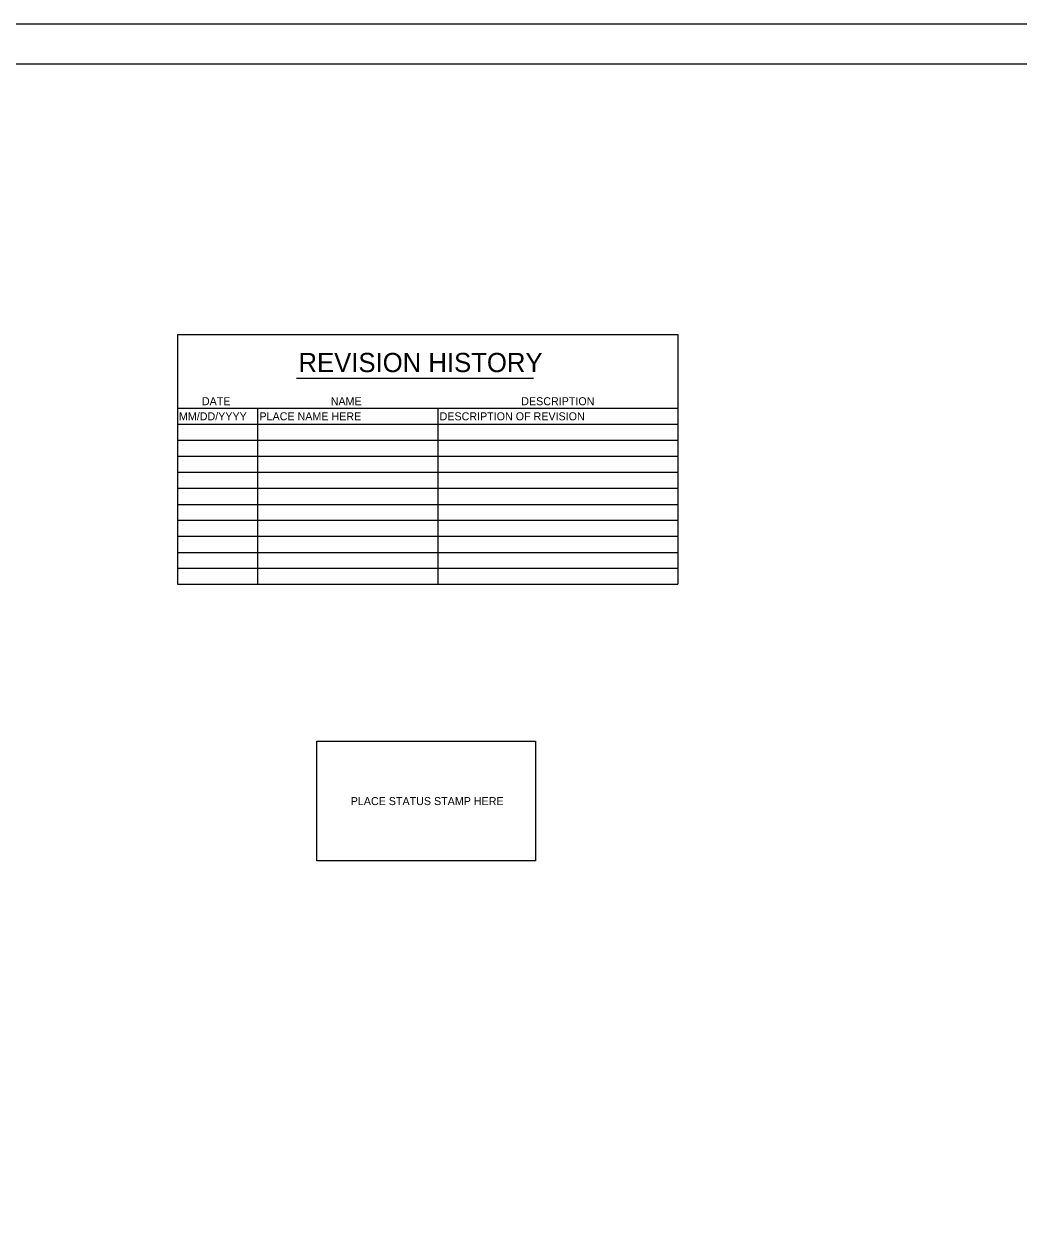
# Model space of a CAD drawing. Extents: x -1.2 to 17.3, y -1 to 2.5.
# Drawn here: x 0.975 to 2.01, y 0.739 to 2 of the extents above; entities that cross this region are included whole.
import ezdxf

# ---------------------------------------------------------------- set-up
doc = ezdxf.new("R2010")
doc.units = 0
for name, color, linetype in [('#plot_shape', 7, 'Continuous'), ('P_ODOT_PLAN_Border', 7, 'Continuous'), ('P_ODOT_PLAN_General', 7, 'Continuous')]:
    doc.layers.add(name, color=color, linetype=linetype)

msp = doc.modelspace()

# ---------------------------------------------------------------- linework, layer by layer
at = {"layer": '#plot_shape'}
msp.add_lwpolyline([(0, 0), (16.6667, 0), (16.6667, 2), (0, 2)], close=True, dxfattribs=at)
msp.add_lwpolyline([(0, 0), (16.6667, 0), (16.6667, 2), (0, 2)], close=True, dxfattribs=at)
at = {"layer": 'P_ODOT_PLAN_Border'}
for p, q in [((1.134, 1.6769), (1.134, 1.4167)), ((1.134, 1.6769), (1.6549, 1.6769)), ((1.134, 1.6769), (1.134, 1.4167)), ((1.134, 1.6769), (1.6549, 1.6769)), ((1.6549, 1.6769), (1.6549, 1.4167)), ((1.6549, 1.6769), (1.6549, 1.4167)), ((1.258, 1.6315), (1.5045, 1.6315)), ((1.258, 1.6315), (1.5045, 1.6315)), ((1.134, 1.6), (1.6549, 1.6)), ((1.134, 1.6), (1.6549, 1.6)), ((1.2174, 1.6), (1.2174, 1.4167)), ((1.2174, 1.6), (1.2174, 1.4167)), ((1.4049, 1.6), (1.4049, 1.4167)), ((1.4049, 1.6), (1.4049, 1.4167)), ((1.134, 1.5834), (1.6549, 1.5834)), ((1.134, 1.5834), (1.6549, 1.5834)), ((1.134, 1.5667), (1.6549, 1.5667)), ((1.134, 1.5667), (1.6549, 1.5667)), ((1.134, 1.55), (1.6549, 1.55)), ((1.134, 1.55), (1.6549, 1.55)), ((1.134, 1.5334), (1.6549, 1.5334)), ((1.134, 1.5334), (1.6549, 1.5334)), ((1.134, 1.5167), (1.6549, 1.5167)), ((1.134, 1.5167), (1.6549, 1.5167)), ((1.134, 1.5), (1.6549, 1.5)), ((1.134, 1.5), (1.6549, 1.5)), ((1.134, 1.4834), (1.6549, 1.4834)), ((1.134, 1.4834), (1.6549, 1.4834)), ((1.134, 1.4667), (1.6549, 1.4667)), ((1.134, 1.4667), (1.6549, 1.4667)), ((1.134, 1.45), (1.6549, 1.45)), ((1.134, 1.45), (1.6549, 1.45)), ((1.134, 1.4334), (1.6549, 1.4334)), ((1.134, 1.4334), (1.6549, 1.4334)), ((1.134, 1.4167), (1.6549, 1.4167)), ((1.134, 1.4167), (1.6549, 1.4167))]:
    msp.add_line(p, q, dxfattribs=at)
for points in [[(0.0417, 0.0417), (16.625, 0.0417), (16.625, 1.9583), (0.0417, 1.9583)], [(0.0417, 0.0417), (16.625, 0.0417), (16.625, 1.9583), (0.0417, 1.9583)], [(1.5066, 1.1286), (1.2792, 1.1286), (1.2792, 1.2534), (1.5066, 1.2534)], [(1.5066, 1.1286), (1.2792, 1.1286), (1.2792, 1.2534), (1.5066, 1.2534)]]:
    msp.add_lwpolyline(points, close=True, dxfattribs=at)

# ---------------------------------------------------------------- texts
at = {"layer": 'P_ODOT_PLAN_General'}
for s, height, p in [('REVISION HISTORY', 0.02, (1.26, 1.6377)), ('REVISION HISTORY', 0.02, (1.26, 1.6377)), ('DATE', 0.00833, (1.1595, 1.6032)), ('DATE', 0.00833, (1.1595, 1.6032)), ('NAME', 0.00833, (1.2936, 1.6032)), ('NAME', 0.00833, (1.2936, 1.6032)), ('DESCRIPTION', 0.008333, (1.4919, 1.6032)), ('DESCRIPTION', 0.008333, (1.4919, 1.6032)), ('MM/DD/YYYY', 0.00833, (1.1356, 1.5875)), ('MM/DD/YYYY', 0.00833, (1.1356, 1.5875)), ('PLACE NAME HERE', 0.008333, (1.2194, 1.5875)), ('PLACE NAME HERE', 0.008333, (1.2194, 1.5875)), ('DESCRIPTION OF REVISION', 0.008333, (1.4069, 1.5875)), ('DESCRIPTION OF REVISION', 0.008333, (1.4069, 1.5875)), ('PLACE STATUS STAMP HERE', 0.008333, (1.3144, 1.1868)), ('PLACE STATUS STAMP HERE', 0.008333, (1.3144, 1.1868))]:
    msp.add_text(s, height=height, dxfattribs=at).set_placement(p)

doc.saveas('drawing.dxf')
